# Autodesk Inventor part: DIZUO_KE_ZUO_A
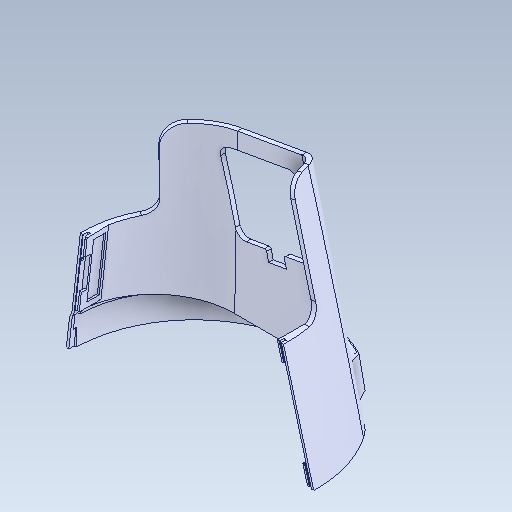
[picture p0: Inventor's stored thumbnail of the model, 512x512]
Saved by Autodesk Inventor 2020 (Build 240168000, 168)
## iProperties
Created: 2017-09
Part Number: DIZUO_KE_ZUO_A
Material: Générique
Document SubType Name: Modeling
Designer: bruno
Density: 1 g/cm^3
Appearance: Par défaut
Author: bruno
Sending System: SolidWorks 2016
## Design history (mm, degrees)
feature "Importée1"
node "Solide1"
